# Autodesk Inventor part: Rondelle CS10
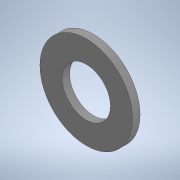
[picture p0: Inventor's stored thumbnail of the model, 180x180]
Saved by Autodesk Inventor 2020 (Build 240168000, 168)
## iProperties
Created: 2003-06
Part Number: Rondelle CS10
Material: Générique
Document SubType Name: Modeling
Designer: Bruno
Density: 1 g/cm^3
Appearance: Par défaut
Author: Bruno
Sending System: SolidWorks 2011
Last Author: Professeur
Last Saved: 2014-11-10
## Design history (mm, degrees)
feature "Base-Extrusion"
node "Solide1"
